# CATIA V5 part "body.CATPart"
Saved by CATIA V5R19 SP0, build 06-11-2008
Part number: body
Bounding box of the stored display mesh (mm): x -52.07 to 52.07, y -30.48 to 30.48, z -10.16 to 0
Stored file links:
  F:\CAD\ipod\body.CATPart
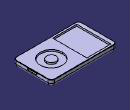
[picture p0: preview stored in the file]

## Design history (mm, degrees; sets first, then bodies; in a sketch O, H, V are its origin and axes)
Body1 (main body)
  Sketch1 on xy-plane, origin (0, 0, 0), H (1, 0, 0), V (0, 1, 0)
    point P1 (-52.07, 30.48)
    line L1 (-46.99, 30.48) -> (46.99, 30.48)
    line L2 (52.07, 25.4) -> (52.07, -25.4)
    line L3 (46.99, -30.48) -> (-46.99, -30.48)
    line L4 (-52.07, -25.4) -> (-52.07, 25.4)
    point P2 (52.07, 30.48)
    point P3 (52.07, -30.48)
    arc A1 centre (-46.99, 25.4) radius 5.08 from (-52.07, 25.4) to (-46.99, 30.48) cw
    arc A2 centre (-46.99, -25.4) radius 5.08 from (-52.07, -25.4) to (-46.99, -30.48) ccw
    arc A3 centre (46.99, 25.4) radius 5.08 from (46.99, 30.48) to (52.07, 25.4) cw
    arc A4 centre (46.99, -25.4) radius 5.08 from (46.99, -30.48) to (52.07, -25.4) ccw
    distance P1 P2 = 104.14
    radius A1 = 5.08
    radius A2 = 5.08
    distance P2 P3 = 60.96
    radius A3 = 5.08
    radius A4 = 5.08
    horizontal: L1 H, L3 H
    vertical: L2 V, L4 V
    symmetry: L1 L3 H, L4 L2 V
    coincidence: L4 P1, L1 P1, L1 P2, L2 P2, L3 P3, L2 P3
    tangency: A1 L4, A1 L1, A2 L4, A2 L3, A3 L1, A3 L2, A4 L3, A4 L2
  Pad1: profile Sketch1, direction (0, 0, -1), length 10.16
  Fillet1: radius 5.08, on edge [end face of Pad1 | face of Pad1 from Sketch1.L1]; edge [end face of Pad1 | face of Pad1 from Sketch1.L3]
  Fillet2: radius 0.508, on edge [face of Pad1 from Sketch1.L1 | start face of Pad1]; edge [face of Pad1 from Sketch1.L2 | start face of Pad1]; edge [face of Pad1 from Sketch1.A3 | start face of Pad1]; start face of Pad1
  Sketch2 on face of Pad1 from Sketch1.L2, origin (52.07, 0, 0), H (0, 1, 0), V (0, 0, 1)
    line L1 (-7.112, -1.524) -> (7.112, -1.524)
    line L2 (7.62, -2.032) -> (7.62, -3.048)
    line L3 (7.112, -3.556) -> (-7.112, -3.556)
    line L4 (-7.62, -3.048) -> (-7.62, -2.032)
    point P1 (7.62, -3.556)
    point P2 (-7.62, -3.556)
    arc A1 centre (-7.112, -2.032) radius 0.508 from (-7.62, -2.032) to (-7.112, -1.524) cw
    arc A2 centre (-7.112, -3.048) radius 0.508 from (-7.62, -3.048) to (-7.112, -3.556) ccw
    arc A3 centre (7.112, -2.032) radius 0.508 from (7.112, -1.524) to (7.62, -2.032) cw
    arc A4 centre (7.112, -3.048) radius 0.508 from (7.112, -3.556) to (7.62, -3.048) ccw
    radius A1 = 0.508
    distance P1 P2 = 15.24
    radius A2 = 0.508
    radius A3 = 0.508
    radius A4 = 0.508
    distance L1 H = 1.524
    length L2 = 1.016
    horizontal: L1 H, L3 H
    vertical: L2 V, L4 V
    symmetry: L4 L2 V
    tangency: A1 L4, A1 L1, A2 L4, A2 L3, A3 L1, A3 L2, A4 L3, A4 L2
    coincidence: L4 P2, L3 P2, L3 P1, L2 P1
  Pocket1: profile Sketch2, direction (-1, 0, 0), length 7.62
  Sketch3 on face of Pad1 from Sketch1.L4, origin (-52.07, 0, 0), H (0, -1, 0), V (0, 0, 1)
    circle A1 centre (-16.9294, -3.048) radius 1.27
    point P1 (-16.9294, -3.048)
    circle A2 centre (-10.0215, -3.048) radius 0.635
    point P2 (-10.0215, -3.048)
    line L1 (4.2495, -2.0917) -> (19.4895, -2.0917)
    line L2 (19.4895, -2.0917) -> (19.4895, -4.0043)
    line L3 (19.4895, -4.0043) -> (4.2495, -4.0043)
    line L4 (4.2495, -4.0043) -> (4.2495, -2.0917)
    axis line L5 (1.3195, -3.048) -> (27.352, -3.048)
    radius A1 = 1.27
    distance P1 H = 3.048
    radius A2 = 0.635
    distance P2 H = 3.048
    length L2 = 1.9126
    length L1 = 15.24
    horizontal: L1 H, L3 H, L5 H
    vertical: L2 V, L4 V
    fix: L5
    symmetry: L1 L3 L5
  Pocket2: profile Sketch3, direction (1, 0, 0), length 2.54
  Sketch4 on start face of Pad1, origin (0, 0, 0), H (1, 0, 0), V (0, 1, 0)
    line L1 (-45.72, 27.0839) -> (-7.62, 27.0839)
    line L2 (-7.62, 27.0839) -> (-7.62, -27.0839)
    line L3 (-7.62, -27.0839) -> (-45.72, -27.0839)
    line L4 (-45.72, -27.0839) -> (-45.72, 27.0839)
    axis line L5 (-26.67, 44.201) -> (-26.67, -59.8013)
    reference projected line E1 (52.07, -25.4) -> (52.07, 25.4) from edge [face of Pad1 from Sketch1.L2 | face of Fillet2]
    circle A1 centre (21.59, 0) radius 17.78
    point P7 (21.59, 0)
    circle A2 centre (21.59, 0) radius 7.62
    reference projected line E2 (52.07, -25.4) -> (52.07, 25.4) from edge [face of Pad1 from Sketch1.L2 | face of Fillet2]
    length L1 = 38.1
    distance L5 E1 = 78.74
    radius A1 = 17.78
    radius A2 = 7.62
    distance P7 E2 = 30.48
    horizontal: L1 H, L3 H
    vertical: L2 V, L4 V, L5 V
    symmetry: L4 L2 L5, L1 L3 H
    coincidence: P7 H
  Pocket3: profile Sketch4, direction (0, 0, -1), length 2.54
